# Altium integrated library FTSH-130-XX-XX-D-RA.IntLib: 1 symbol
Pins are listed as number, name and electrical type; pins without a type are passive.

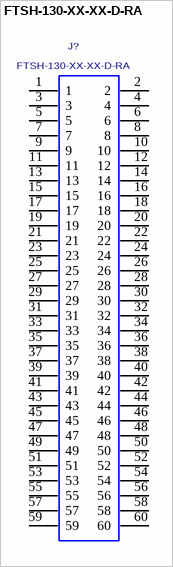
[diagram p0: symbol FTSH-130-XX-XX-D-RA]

## FTSH-130-XX-XX-D-RA
designator J?
.050 x .050 C.L. DOUBLE HORIZONTAL TERMINAL STRIP, 60 PINS.; MANUFACTURER: SAMTEC
footprint FTSH-130-XX-XX-D-RA
pins: 1, 2, 3, 4, 5, 6, 7, 8, 9, 10, 11, 12, 13, 14, 15, 16, 17, 18, 19, 20, 21, 22, 23, 24, 25, 26, 27, 28, 29, 30, 31, 32, 33, 34, 35, 36, 37, 38, 39, 40, 41, 42, 43, 44, 45, 46, 47, 48, 49, 50, 51, 52, 53, 54, 55, 56, 57, 58, 59, 60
